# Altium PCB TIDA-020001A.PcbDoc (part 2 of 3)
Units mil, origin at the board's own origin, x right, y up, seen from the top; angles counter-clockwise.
Board outline 11050 x 5518 mil, 4 copper layers (Top Layer, PWR, GND, Bottom Layer), stack 61.434 mil thick; 283 components, 210 nets, 883 pads, 1184 vias.
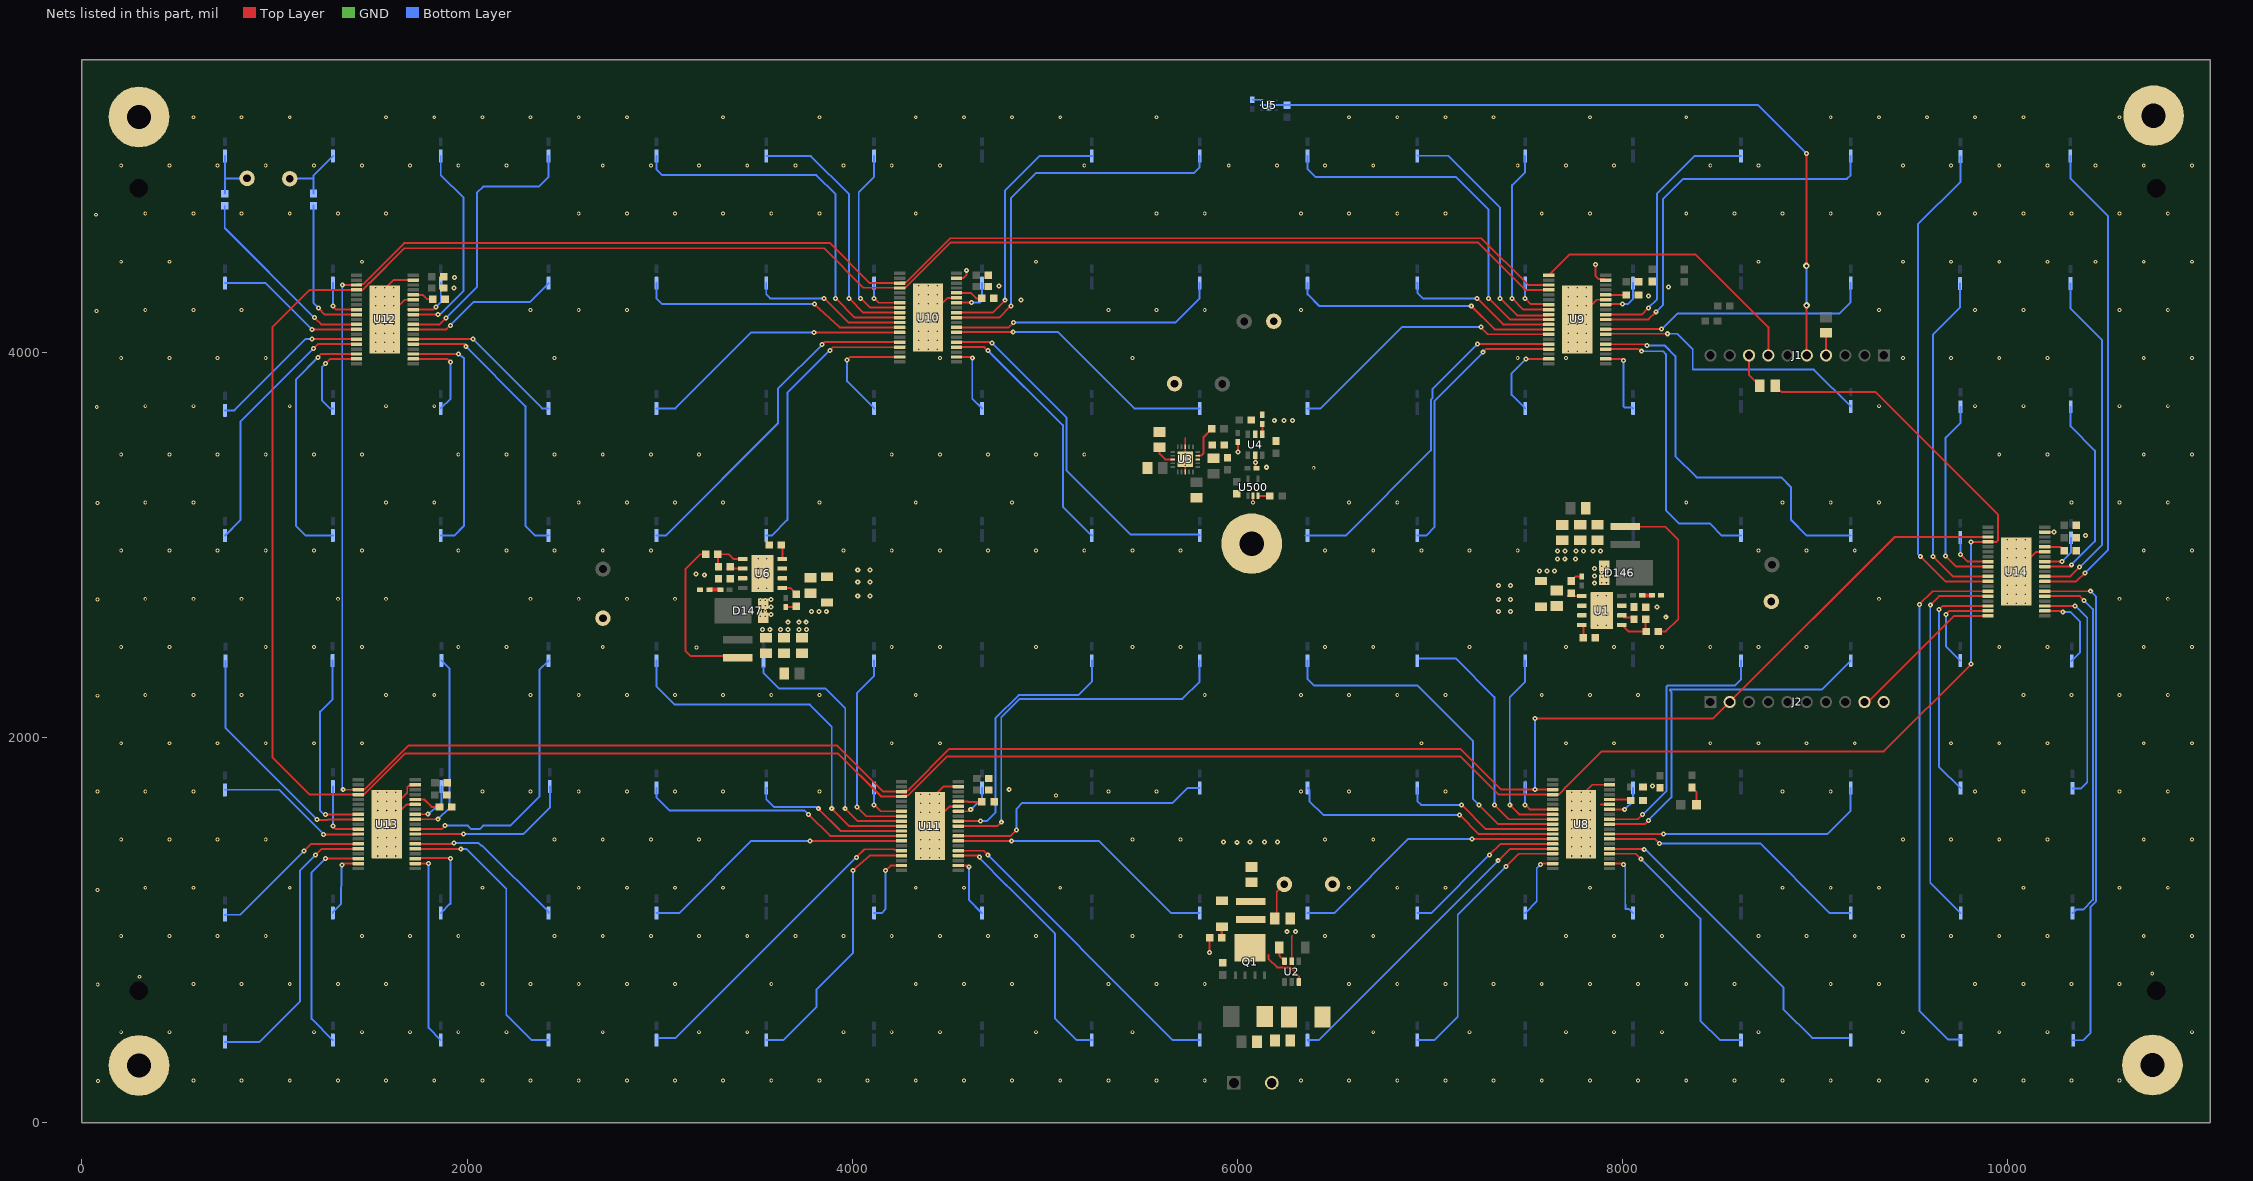
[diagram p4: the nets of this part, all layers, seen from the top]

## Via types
v1: diameter 20, hole 10, Top Layer to Bottom Layer, tented both sides, 504 vias
v2: diameter 26, hole 10, Top Layer to Bottom Layer, tented both sides, 472 vias
v3: diameter 19.68, hole 7.87, Top Layer to Bottom Layer, tented both sides, 205 vias
v4: diameter 34, hole 16, Top Layer to Bottom Layer, tented both sides, 2 vias
v5: diameter 19.68, hole 7.87, Top Layer to Bottom Layer, 1 vias

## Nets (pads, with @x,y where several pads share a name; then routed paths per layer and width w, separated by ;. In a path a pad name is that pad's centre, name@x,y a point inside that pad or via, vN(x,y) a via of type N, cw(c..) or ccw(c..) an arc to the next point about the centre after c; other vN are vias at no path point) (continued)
GCLK: R27.1 U8.4 U9.4 U10.4 U11.4 U12.4 U13.4 U14.4 | length 21192.8
  Top Layer w10: U9.4@7615.92,4323.25 7493.68,4323.25 7247.05,4569.88 4511.18,4569.88 4274.55,4333.25 U10.4@4245.92,4333.25 4244.53,4334.65 4058.07,4334.65 3853.35,4539.37 1674.21,4539.37 1493.72,4358.88 1490.77,4358.88 1482.82,4350.92 1482.82,4347.98 1458.1,4323.25 U12.4@1425.92,4323.25 1183.49,4323.25 989.17,4128.94 989.17,1896.65 1182.09,1703.74 1346.53,1703.74 1346.93,1703.35 1367.64,1703.35 1368.03,1703.74 1435.44,1703.74 U13.4@1435.92,1703.25 1464.55,1703.25 1677.63,1916.34 3927.17,1916.34 4150.25,1693.25 U11.4@4255.92,1693.25 4260.65,1697.99 4289.28,1697.99 4492.87,1901.57 7156.74,1901.57 7355.06,1703.25 U8.4@7635.92,1703.25 7666.84,1703.25 7692.82,1729.24 7692.82,1730.92 7700.77,1738.88 7702.46,1738.88 7890.75,1927.17 9355.32,1927.17 v2(9809.06,2380.91) ; R27.1@8790.98,3825.79 8823.46,3793.31 9312.01,3793.31 9948.82,3156.5 9948.82,3023.62 9939.96,3014.76 9896.15,3014.76 U14.4@9896.04,3014.87 v2(9809.06,3014.87)
  Bottom Layer w10: v2(9809.06,2380.91) v2(9809.06,3014.87)
GND: C1.2 C4.2 C5.1 C7.2 C8.2 C9.2 C11.2 C12.2 C13.2 C14.2 C15.2 C16.2 C17.2 C19.2 C21.2 C22.1 C23.2 C24.2 C25.2 C26.2 C27.2 C28.2 C29.2 C30.2 C31.2 C40.2 C41.2 C42.2 C43.2 C44.2 C45.2 C46.2 C47.2 C48.2 C49.2 C77.2 C88.2 C500.2 D145.1 D146.1 D146.2 D147.1 D147.2 H1.1 H2.1 H3.1 H4.1 H5.1 J2.10 R3.1 R5.1 R7.1 R8.1 R10.1 R11.1 R12.1 R14.1 R16.1 R18.1 R22.1 R23.1 R25.1 R31.1 TP4.1 TP5.1 TP7.1 TP9.1 TP11.1 U1.7 U1.9@7891.73,2658.86 U2.2 U3.8 U3.18 U3.21 U4.2 U5.2 U5.3 U5.7 U6.7 U6.9@3534.15,2851.35 U8.33 U8.37 U8.39 U9.33 U9.37 U9.39 U10.33 U10.37 U10.39 U11.33 U11.37 U11.39 U12.33 U12.37 U12.39 U13.33 U13.37 U13.39 U14.33 U14.37 U14.39 U500.2 Vbatt1.2 | length 3313.3
  Top Layer w10: U12.39@1573.56,4169.71 1675.92,4272.07 U12.33@1721.2,4272.07 ; v3(1573.56,4193.33) v3(1573.56,4240.58) v3(1573.56,4287.82) 1573.56,4330.45 1617.54,4374.43 U12.37@1721.2,4374.43 ; U13.33@1731.2,1652.07 1685.92,1652.07 U13.39@1583.56,1549.71 v3(1583.56,1573.33) 1583.56,1606.8 1689.67,1712.91 1689.67,1741.53 1697.84,1749.7 1726.47,1749.7 U13.37@1731.2,1754.43 ; U10.39@4393.56,4179.71 4495.92,4282.07 U10.33@4541.2,4282.07 ; v3(4393.56,4297.82) U10.39@4393.56,4300.56 ; U10.37@4541.2,4384.43 4576.2,4384.43 4576.77,4383.86 4592.52,4399.61 v2(4592.52,4425.2) ; U11.33@4551.2,1642.07 4505.92,1642.07 U11.39@4403.56,1539.71 v3(4403.56,1563.33) v3(4403.56,1610.58) v3(4403.56,1657.82) 4403.56,1675.21 4472.78,1744.43 U11.37@4551.2,1744.43 ; U3.18@5728.93,3378.02 v3(5728.93,3412.47) U3.21@5728.93,3442.98 v3(5728.93,3473.49) U3.8@5728.93,3507.94 5728.93,3554.87 ; v2(5855.31,883.86) R31.1@5855.31,959.65 ; C9.2@6000.94,3533.68 6002.95,3531.67 v2(6002.95,3482.28) ; v1(6079.72,3219.64) 6080.71,3220.62 U500.2@6080.71,3253.94 ; U4.2@6091.8,3465.42 6093.5,3448.82 v2(6093.5,3427.17) 6093.5,3425.2 6093.5,3409.43 C7.2@6099.41,3397.64 ; U2.2@6281.5,838.58 6281.5,967.52 6282.17,968.19 ; U9.39@7763.56,4169.71 7865.92,4272.07 U9.33@7911.2,4272.07 ; U8.39@7783.56,1549.71 v3(7783.56,1573.33) v3(7783.56,1620.58) v3(7783.56,1667.82) 7783.56,1696.95 7841.05,1754.43 U8.37@7931.2,1754.43 ; v2(7858.87,4455.79) 7858.27,4396.69 7875.75,4379.2 ; 7875.75,4379.17 7906.47,4379.17 U9.37@7911.2,4374.43 ; 7885.92,1652.07 U8.33@7931.2,1652.07 ; U14.39@10043.68,2861.33 10146.04,2963.69 U14.33@10191.32,2963.69 ; U14.37@10191.32,3066.05 10192.19,3066.93 v2(10238.19,3066.93)
  GND w10: v3@10089.36,2981 v3(10090.92,2979.44) v3@10092.81,2981.32
  Bottom Layer w10: C11.2@6077.34,5310.63 6123.62,5310.63 U5.3@6126.23,5308.02 U5.2@6126.23,5282.24 U5.7@6163.63,5282.24
  other v1: 83.66,215.55 579.72,219.64 829.72,219.64 1079.72,219.64 1329.72,219.64 1579.72,219.64 1829.72,219.64 2079.72,219.64 2329.72,219.64 2579.72,219.64 2829.72,219.64 3079.72,219.64 3329.72,219.64 3579.72,219.64 3829.72,219.64 4079.72,219.64 4329.72,219.64 4579.72,219.64 4829.72,219.64 5079.72,219.64 5329.72,219.64 5579.72,219.64 5829.72,219.64 6329.72,219.64 6579.72,219.64 6829.72,219.64 7079.72,219.64 7329.72,219.64 7579.72,219.64 7829.72,219.64 8079.72,219.64 8329.72,219.64 8579.72,219.64 8829.72,219.64 9079.72,219.64 9329.72,219.64 9579.72,219.64 9829.72,219.64 10079.72,219.64 10329.72,219.64 10579.72,219.64 204.72,469.64 454.72,469.64 1204.72,469.64 1454.72,469.64 1704.72,469.64 1954.72,469.64 2204.72,469.64 2704.72,469.64 3204.72,469.64 3454.72,469.64 3954.72,469.64 4204.72,469.64 4454.72,469.64 4954.72,469.64 5454.72,469.64 6704.72,469.64 7204.72,469.64 7704.72,469.64 7954.72,469.64 8204.72,469.64 8704.72,469.64 9454.72,469.64 9954.72,469.64 10204.72,469.64 10954.72,469.64 82.68,716.54 579.72,719.64 829.72,719.64 1079.72,719.64 1329.72,719.64 1579.72,719.64 2079.72,719.64 2329.72,719.64 2579.72,719.64 2829.72,719.64 3079.72,719.64 3579.72,719.64 4329.72,719.64 4579.72,719.64 4829.72,719.64 5329.72,719.64 5579.72,719.64 5829.72,719.64 6579.72,719.64 6829.72,719.64 7079.72,719.64 7329.72,719.64 7579.72,719.64 7829.72,719.64 8079.72,719.64 8329.72,719.64 8579.72,719.64 9079.72,719.64 9329.72,719.64 9829.72,719.64 10079.72,719.64 10329.72,719.64 10579.72,719.64 300.2,757.41 10749.02,773.62 204.72,969.64 454.72,969.64 704.72,969.64 954.72,969.64 1454.72,969.64 1704.72,969.64 1954.72,969.64 2454.72,969.64 2704.72,969.64 2954.72,969.64 3204.72,969.64 3454.72,969.64 3704.72,969.64 3954.72,969.64 4204.72,969.64 4454.72,969.64 4704.72,969.64 4954.72,969.64 5454.72,969.64 5704.72,969.64 6454.72,969.64 6704.72,969.64 7704.72,969.64 7954.72,969.64 8204.72,969.64 8704.72,969.64 8954.72,969.64 9204.72,969.64 9454.72,969.64 9704.72,969.64 9954.72,969.64 10204.72,969.64 10704.72,969.64 10954.72,969.64 81.69,1207.68 329.72,1219.64 579.72,1219.64 1079.72,1219.64 2079.72,1219.64 2579.72,1219.64 2829.72,1219.64 3079.72,1219.64 3329.72,1219.64 4329.72,1219.64 4579.72,1219.64 5079.72,1219.64 6579.72,1219.64 6829.72,1219.64 7079.72,1219.64 7829.72,1219.64 8829.72,1219.64 9079.72,1219.64 9329.72,1219.64 10079.72,1219.64 10579.72,1219.64 10829.72,1219.64 204.72,1469.64 454.72,1469.64 704.72,1469.64 954.72,1469.64 2454.72,1469.64 2704.72,1469.64 2954.72,1469.64 3204.72,1469.64 5454.72,1469.64 5704.72,1469.64 6454.72,1469.64 6704.72,1469.64 9454.72,1469.64 9704.72,1469.64 9954.72,1469.64 10204.72,1469.64 10704.72,1469.64 10954.72,1469.64 5058.07,1698.82 81.69,1719.49 329.72,1719.64 579.72,1719.64 2079.72,1719.64 2329.72,1719.64 2579.72,1719.64 2829.72,1719.64 3079.72,1719.64 3329.72,1719.64 3829.72,1719.64 5329.72,1719.64 5579.72,1719.64 6329.72,1719.64 6579.72,1719.64 7079.72,1719.64 8829.72,1719.64 9079.72,1719.64 9829.72,1719.64 10079.72,1719.64 10579.72,1719.64 10829.72,1719.64 204.72,1969.64 454.72,1969.64 704.72,1969.64 954.72,1969.64 1204.72,1969.64 1454.72,1969.64 4204.72,1969.64 4454.72,1969.64 6954.72,1969.64 7704.72,1969.64 7954.72,1969.64 8454.72,1969.64 8704.72,1969.64 8954.72,1969.64 9204.72,1969.64 9704.72,1969.64 9954.72,1969.64 10204.72,1969.64 10704.72,1969.64 10954.72,1969.64 81.69,2216.54 329.72,2219.64 579.72,2219.64 829.72,2219.64 1579.72,2219.64 1829.72,2219.64 2329.72,2219.64 2579.72,2219.64 2829.72,2219.64 3079.72,2219.64 3329.72,2219.64 3579.72,2219.64 3829.72,2219.64 4329.72,2219.64 5829.72,2219.64 6329.72,2219.64 6579.72,2219.64 6829.72,2219.64 7079.72,2219.64 7579.72,2219.64 7829.72,2219.64 8079.72,2219.64 10079.72,2219.64 10329.72,2219.64 10579.72,2219.64 10829.72,2219.64 3190.94,2466.69 204.72,2469.64 454.72,2469.64 954.72,2469.64 1204.72,2469.64 1454.72,2469.64 1954.72,2469.64 2204.72,2469.64 2704.72,2469.64 4204.72,2469.64 4454.72,2469.64 4954.72,2469.64 5454.72,2469.64 5704.72,2469.64 6454.72,2469.64 6704.72,2469.64 7204.72,2469.64 7704.72,2469.64 7954.72,2469.64 8204.72,2469.64 8454.72,2469.64 8704.72,2469.64 8954.72,2469.64 9954.72,2469.64 10204.72,2469.64 10704.72,2469.64 10954.72,2469.64 81.69,2715.55 329.72,2719.64 579.72,2719.64 829.72,2719.64 1329.72,2719.64 1579.72,2719.64 2329.72,2719.64 2579.72,2719.64 2829.72,2719.64 3079.72,2719.64 9329.72,2719.64 10579.72,2719.64 10829.72,2719.64 204.72,2969.64 454.72,2969.64 704.72,2969.64 954.72,2969.64 1204.72,2969.64 1454.72,2969.64 1954.72,2969.64 2204.72,2969.64 2454.72,2969.64 2704.72,2969.64 2954.72,2969.64 3954.72,2969.64 4204.72,2969.64 4454.72,2969.64 4704.72,2969.64 4954.72,2969.64 5204.72,2969.64 5454.72,2969.64 5704.72,2969.64 6454.72,2969.64 6704.72,2969.64 6954.72,2969.64 7204.72,2969.64 7454.72,2969.64 8704.72,2969.64 8954.72,2969.64 9204.72,2969.64 10704.72,2969.64 10954.72,2969.64 81.69,3216.54 329.72,3219.64 579.72,3219.64 1579.72,3219.64 1829.72,3219.64 2579.72,3219.64 2829.72,3219.64 3079.72,3219.64 3329.72,3219.64 3829.72,3219.64 4329.72,3219.64 4829.72,3219.64 6579.72,3219.64 6829.72,3219.64 8329.72,3219.64 8829.72,3219.64 9079.72,3219.64 9329.72,3219.64 10329.72,3219.64 10579.72,3219.64 10829.72,3219.64 6395.67,3399.61 204.72,3469.64 454.72,3469.64 704.72,3469.64 954.72,3469.64 1204.72,3469.64 1454.72,3469.64 1954.72,3469.64 2204.72,3469.64 2454.72,3469.64 2704.72,3469.64 2954.72,3469.64 3204.72,3469.64 4204.72,3469.64 4454.72,3469.64 4704.72,3469.64 4954.72,3469.64 5204.72,3469.64 9954.72,3469.64 10204.72,3469.64 10704.72,3469.64 10954.72,3469.64 77.76,3714.57 329.72,3719.64 579.72,3719.64 1079.72,3719.64 1579.72,3719.64 1829.72,3719.64 9329.72,3719.64 9829.72,3719.64 10079.72,3719.64 10579.72,3719.64 10829.72,3719.64 204.72,3969.64 454.72,3969.64 704.72,3969.64 954.72,3969.64 2454.72,3969.64 4454.72,3969.64 5454.72,3969.64 7454.72,3969.64 7704.72,3969.64 9454.72,3969.64 9704.72,3969.64 9954.72,3969.64 10204.72,3969.64 10704.72,3969.64 10954.72,3969.64 76.77,4213.58 329.72,4219.64 579.72,4219.64 829.72,4219.64 2329.72,4219.64 2579.72,4219.64 2829.72,4219.64 5329.72,4219.64 5579.72,4219.64 5829.72,4219.64 6329.72,4219.64 9329.72,4219.64 9829.72,4219.64 10079.72,4219.64 10579.72,4219.64 10829.72,4219.64 204.72,4469.64 454.72,4469.64 1454.72,4469.64 4954.72,4469.64 8704.72,4469.64 9454.72,4469.64 9704.72,4469.64 9954.72,4469.64 10204.72,4469.64 10454.72,4469.64 10704.72,4469.64 10954.72,4469.64 73.82,4713.58 329.72,4719.64 579.72,4719.64 829.72,4719.64 1079.72,4719.64 1329.72,4719.64 1579.72,4719.64 2579.72,4719.64 2829.72,4719.64 3079.72,4719.64 3329.72,4719.64 3579.72,4719.64 3829.72,4719.64 4329.72,4719.64 5579.72,4719.64 5829.72,4719.64 6329.72,4719.64 6579.72,4719.64 6829.72,4719.64 7079.72,4719.64 7579.72,4719.64 7829.72,4719.64 8329.72,4719.64 8579.72,4719.64 8829.72,4719.64 9079.72,4719.64 9329.72,4719.64 9829.72,4719.64 10079.72,4719.64 10329.72,4719.64 10579.72,4719.64 10829.72,4719.64 204.72,4969.64 454.72,4969.64 704.72,4969.64 954.72,4969.64 1204.72,4969.64 1454.72,4969.64 1704.72,4969.64 1954.72,4969.64 2204.72,4969.64 2704.72,4969.64 2954.72,4969.64 3204.72,4969.64 3454.72,4969.64 3704.72,4969.64 3954.72,4969.64 4204.72,4969.64 4454.72,4969.64 5204.72,4969.64 5954.72,4969.64 6204.72,4969.64 6454.72,4969.64 6704.72,4969.64 7454.72,4969.64 7704.72,4969.64 7954.72,4969.64 8454.72,4969.64 8704.72,4969.64 9454.72,4969.64 9704.72,4969.64 9954.72,4969.64 10204.72,4969.64 10454.72,4969.64 10704.72,4969.64 10954.72,4969.64 579.72,5219.64 829.72,5219.64 1079.72,5219.64 1579.72,5219.64 1829.72,5219.64 2079.72,5219.64 2329.72,5219.64 2579.72,5219.64 2829.72,5219.64 3329.72,5219.64 3829.72,5219.64 4329.72,5219.64 4579.72,5219.64 4829.72,5219.64 5079.72,5219.64 5579.72,5219.64 6579.72,5219.64 6829.72,5219.64 7079.72,5219.64 7329.72,5219.64 7829.72,5219.64 8329.72,5219.64 9079.72,5219.64 9329.72,5219.64 9579.72,5219.64 9829.72,5219.64 10079.72,5219.64 10579.72,5219.64
  other v2: 6257.87,991.14 6300.24,991.14 4814.96,1730.32 8154.53,1747.05 3533.46,2560.04 3571.79,2560.04 3627.95,2561.02 3667.32,2561.02 3723.43,2561.02 3761.75,2561.02 3667.11,2598.04 3722.9,2598.04 3760.99,2598.04 8223.43,2624.02 3578.14,2638.95 3788.5,2653.54 3826.83,2653.54 3865.16,2653.54 8177.17,2676.18 3578.14,2677.28 3578.14,2715.61 7854.25,2800.47 7854.25,2838.8 3231.8,2842.35 3189.47,2847.54 7568.96,2864.17 7607.28,2864.17 7645.61,2864.17 7854.25,2877.13 7660.94,2925.52 7699.03,2925.52 7754.82,2925.52 7846.46,2967.52 7884.78,2967.52 7662.4,2968.5 7700.73,2968.5 7758.11,2968.5 7796.44,2968.5 10401.57,3048.23 6150.59,3402.56 6190.94,3644.69 6241.14,3644.69 6286.42,3644.69 4875.85,4271.05 8134.84,4292.32 1933.07,4333.66 8237.2,4338.58 4760.83,4342.52 1934.06,4387.8
  other v3: 4356.32,1374.36 4403.56,1374.36 4450.8,1374.36 1536.32,1384.36 1583.56,1384.36 1630.8,1384.36 7736.32,1384.36 7783.56,1384.36 7830.81,1384.36 4356.32,1421.6 4403.56,1421.6 4450.8,1421.6 1536.32,1431.6 1583.56,1431.6 1630.8,1431.6 7736.32,1431.6 7783.56,1431.6 7830.81,1431.6 4356.32,1468.84 4403.56,1468.84 4450.8,1468.84 1536.32,1478.84 1583.56,1478.84 1630.8,1478.84 7736.32,1478.84 7783.56,1478.84 7830.81,1478.84 4356.32,1516.09 4403.56,1516.09 4450.8,1516.09 1536.32,1526.09 1630.8,1526.09 7736.32,1526.09 7783.56,1526.09 7830.81,1526.09 4356.32,1563.33 4450.8,1563.33 1536.32,1573.33 1630.8,1573.33 7736.32,1573.33 7830.81,1573.33 4356.32,1610.58 4450.8,1610.58 1536.32,1620.58 1583.56,1620.58 1630.8,1620.58 7736.32,1620.58 7830.81,1620.58 4356.32,1657.82 4450.8,1657.82 1536.32,1667.82 1583.56,1667.82 1630.8,1667.82 7736.32,1667.82 7830.81,1667.82 4356.32,1705.06 4403.56,1705.06 4450.8,1705.06 1536.32,1715.06 1583.56,1715.06 1630.8,1715.06 7736.32,1715.06 7783.56,1715.06 7830.81,1715.06 7870.08,2582.09 7913.39,2582.09 3522.55,2627.86 3548.16,2627.82 7870.08,2633.27 7913.39,2633.27 3522.55,2656.99 3548.14,2656.99 3522.4,2684.06 3548.01,2684.01 7870.08,2684.45 7913.39,2684.45 9996.43,2695.97 10043.68,2695.97 10090.92,2695.97 3522.4,2713.19 3547.99,2713.19 7870.08,2735.63 7913.39,2735.63 9996.43,2743.22 10043.68,2743.22 10090.92,2743.22 3512.5,2774.57 3555.8,2774.57 9996.43,2790.46 10043.68,2790.46 10090.92,2790.46 7890.08,2802.88 7915.69,2802.84 3512.5,2825.76 3555.8,2825.76 7890.08,2832.02 7915.67,2832.02 9996.43,2837.71 10043.68,2837.71 10090.92,2837.71 7889.93,2859.08 7915.54,2859.04 3512.5,2876.94 3555.8,2876.94 9996.43,2884.95 10043.68,2884.95 10090.92,2884.95 7889.93,2888.21 7915.52,2888.21 3512.5,2928.12 3555.8,2928.12 9996.43,2932.19 10043.68,2932.19 10090.92,2932.19 9996.43,2979.44 10043.68,2979.44 9996.43,3026.68 10043.68,3026.68 10090.92,3026.68 5698.42,3442.98 5759.44,3442.98 1526.32,4004.36 1573.56,4004.36 1620.81,4004.36 7716.32,4004.36 7763.56,4004.36 7810.8,4004.36 4346.32,4014.36 4393.56,4014.36 4440.8,4014.36 1526.32,4051.6 1573.56,4051.6 1620.81,4051.6 7716.32,4051.6 7763.56,4051.6 7810.8,4051.6 4346.32,4061.6 4393.56,4061.6 4440.8,4061.6 1526.32,4098.84 1573.56,4098.84 1620.81,4098.84 7716.32,4098.84 7763.56,4098.84 7810.8,4098.84 4346.32,4108.84 4393.56,4108.84 4440.8,4108.84 1526.32,4146.09 1573.56,4146.09 1620.81,4146.09 7716.32,4146.09 7763.56,4146.09 7810.8,4146.09 4346.32,4156.09 4393.56,4156.09 4440.8,4156.09 1526.32,4193.33 1620.81,4193.33 7716.32,4193.33 7763.56,4193.33 7810.8,4193.33 4346.32,4203.33 4393.56,4203.33 4440.8,4203.33 1526.32,4240.58 1620.81,4240.58 7716.32,4240.58 7763.56,4240.58 7810.8,4240.58 4346.32,4250.58 4393.56,4250.58 4440.8,4250.58 1526.32,4287.82 1620.81,4287.82 7716.32,4287.82 7763.56,4287.82 7810.8,4287.82 4346.32,4297.82 4440.8,4297.82 1526.32,4335.06 1573.56,4335.06 1620.81,4335.06 7716.32,4335.06 7763.56,4335.06 7810.8,4335.06 4346.32,4345.06 4393.56,4345.06 4440.8,4345.06 6163.63,5266.49 6163.63,5297.99
  other v5: 1583.56,1526.09
INT: J1.5 R17.1 U5.5 | length 3905.9
  Top Layer w10: v4(8953.74,4447.83) v2(8953.74,5031.5) ; v4(8954.72,4243.11) 8954.72,3984.28 J1.5@8955.68,3983.33
  Bottom Layer w10: U5.5@6201.03,5282.24 6256.54,5282.24 R17.1@6256.97,5282.67 8702.57,5282.67 v2(8953.74,5031.5) ; v4(8953.74,4447.83) 8953.74,4244.09 v4(8954.72,4243.11)
LATCH: J2.2 U8.3 U9.3 U10.3 U11.3 U12.3 U13.3 U14.3 | length 19026.5
  Top Layer w10: v2(1352.36,4348.43) 1421.98,4348.43 1424.16,4350.61 U12.3@1425.92,4348.84 1430.66,4353.58 1461.43,4353.58 1673.8,4565.94 3884.84,4565.94 4091.94,4358.84 U10.3@4245.92,4358.84 4250.65,4363.58 4280.83,4363.58 4508.79,4591.54 7265.75,4591.54 7508.44,4348.84 U9.3@7615.92,4348.84 ; v2(1357.28,1728.35) 1434.45,1728.35 1435.44,1729.33 U13.3@1435.92,1728.84 1466.1,1728.84 1694.93,1957.68 3923.23,1957.68 4162.06,1718.84 U11.3@4255.92,1718.84 4260.65,1723.58 4289.28,1723.58 4297.45,1731.75 4297.45,1734.46 4503.94,1940.94 7157.48,1940.94 7369.09,1729.33 7544.3,1729.33 v2(7544.79,1728.84) U8.3@7635.92,1728.84 ; v2(7544.29,2098.43) 8469.43,2098.43 J2.2@8555,2184 9411.46,3040.46 9831.66,3040.46 9832.16,3039.96 9852.88,3039.96 9853.38,3040.46 U14.3@9896.04,3040.46
  Bottom Layer w10: v2(1352.36,4348.43) 1352.36,1733.27 v2(1357.28,1728.35) ; v2(7544.29,2098.43) 7544.79,2097.93 v2(7544.79,1728.84)
MISO: J2.9 U14.19 | length 826.2
  Top Layer w10: J2.9@9255,2184 9273.57,2184 9720.58,2631.01 U14.19@9896.04,2631.01
MOSI: J1.7 U9.1 | length 1486.9
  Top Layer w10: U9.1@7615.92,4400.03 7722.79,4506.89 8378.94,4506.89 8755.68,4130.15 J1.7@8755.68,3983.33
NetC1_1: C1.1 R6.2 | length 58.4
  Top Layer w20: R6.2@8093.5,2737.2 8151.83,2737.2 C1.1@8151.87,2737.25
NetC2_1: C2.1 U1.1 | length 74.1
  Top Layer w10: C2.1@7714.33,2733.86 U1.1@7788.39,2733.86
NetC2_2: C2.2 R28.1 | length 63.9
  Top Layer w10: C2.2@7732.28,2812.01 7755.91,2835.63 R28.1@7786.42,2835.63
NetC3_2: C3.2 C12.1
NetC4_1: C4.1 C5.2 C21.1 C22.2 R29.2 U1.2 U1.3 U6.2 U6.3
  other v2: 5997.05,1455.71 5927.17,1456.69 6065.94,1456.69 6139.76,1456.69 6207.68,1457.68 7355.31,2654.53 7418.31,2654.53 7355.31,2716.54 7418.31,2716.54 4028.54,2734.25 4091.54,2734.25 7355.31,2789.37 7418.31,2789.37 4028.54,2807.09 4091.54,2807.09 4028.54,2869.09 4091.54,2869.09
NetC6_2: C6.2 U2.1 | length 82.3
  Top Layer w10: C6.2@6217.02,909.7 6217.02,865.65 U2.1@6244.09,838.58
NetC8_1: C8.1 U4.4 | length 54.5
  Top Layer w10: C8.1@6128.88,3628 6128.88,3574 U4.4@6129.2,3573.69
NetC10_2: C10.2 R2.1 R3.2 U3.3
NetC13_1: C13.1 U1.6 | length 74.4
  Top Layer w10: U1.6@7995.08,2633.86 8005.91,2623.03 C13.1@8064.96,2623.03
NetC14_1: C14.1 C15.1 C16.1 L2.2 R9.1 R30.1 | length 845.1
  Top Layer w10: L2.2@8013.78,3094.87 8015.14,3093.5 8221.46,3093.5 8288.39,3026.57 8288.39,2804.13 8288.39,2614.17 8224.41,2550.2 R9.1@8185.04,2550.2
NetC17_1: C17.1 L1.1 Q1.5 R1.2 TP2.1 U2.4 | length 440.7
  Top Layer w10: 6160.51,871.77 6160.51,851.3 6205.71,806.1 6272.64,806.1 6318.9,759.84 U2.4@6318.9,730.31 ; C17.1@6203.74,1059.06 6203.74,1197.83 TP2.1@6243.11,1237.2
NetC18_1: C18.1 L1.2 R29.1
NetC18_2: C18.2 R31.2 | length 58.5
  Top Layer w12: R31.2@5918.31,959.65 5918.31,1016.73 C18.2@5919.29,1017.72
NetC19_1: C19.1 R19.2 | length 57.5
  Top Layer w20: C19.1@3257.87,2767.72 3313.98,2767.72 R19.2@3314.96,2766.73
NetC20_1: C20.1 U6.1 | length 85.5
  Top Layer w10: U6.1@3637.5,2776.35 3677.39,2776.35 C20.1@3709.65,2744.09
NetC20_2: C20.2 R32.1 | length 52.2
  Top Layer w10: R32.1@3657.48,2677.17 C20.2@3709.65,2677.17
NetC23_1: C23.1 U6.6 | length 77.5
  Top Layer w10: C23.1@3353.35,2876.35 U6.6@3430.8,2876.35
NetC26_1: C26.1 C27.1 C28.1 L3.2 R21.1 R33.1 | length 798
  Top Layer w10: R21.1@3239.17,2950.79 3210.63,2950.79 3133.86,2874.02 3133.86,2448.82 3161.06,2421.62 L3.2@3358.27,2422.44
NetC31_1: C31.1 U3.13 | length 114.8
  Top Layer w10: C31.1@5595.18,3505.91 5595.18,3471.91 5624.1,3442.98 U3.13@5663.97,3442.98
NetD01_1: D01.1 R57.1 | length 99.8
  Top Layer w10: R57.1@8359.25,1740.16 8383.86,1715.55 D01.1@8383.86,1650.59
NetD145_2: D145.2 D148.2
NetJ1_4: J1.4 R26.2 | length 116.7
  Top Layer w10: J1.4@9055.92,3983.57 R26.2@9055.92,4100.3
NetJ1_8: J1.8 R27.2 | length 180.4
  Top Layer w10: J1.8@8655.68,3983.33 8655.68,3881.09 R27.2@8710.98,3825.79
NetR4_1: R4.1 U4.5
NetR5_2: R5.2 U9.34 | length 107.5
  Top Layer w10: U9.34@7911.2,4297.24 R5.2@8018.7,4297.24
NetR7_2: R7.2 U11.34 | length 120.5
  Top Layer w10: U11.34@4551.2,1667.66 4600.05,1667.66 4603.35,1664.37 R7.2@4670.3,1664.37
NetR8_2: R8.2 U12.34 | length 114.6
  Top Layer w10: U12.34@1721.2,4297.66 1769.27,4297.66 1792.32,4274.61 R8.2@1826.28,4274.61
NetR9_2: R9.2 R14.2 U1.5 | length 219.7
  Top Layer w10: U1.5@7995.08,2583.86 8028.74,2550.2 R9.2@8131.91,2550.2 ; R9.2@8119.09,2553.15 R14.2@8119.09,2622.05
NetR10_2: R10.2 U13.34 | length 142.2
  Top Layer w10: U13.34@1731.2,1677.66 1777.06,1677.66 1815.94,1638.78 R10.2@1857.28,1638.78
NetR11_2: R11.2 U1.4 | length 69
  Top Layer w10: U1.4@7788.39,2583.86 7795.28,2576.97 R11.2@7795.28,2517.72
NetR12_2: R12.2 U14.34 | length 109.2
  Top Layer w10: U14.34@10191.32,2989.28 10272.53,2989.28 R12.2@10292.32,2969.49
NetR13_1: R13.1 U500.3 | length 63
  Top Layer w10: U500.3@6105.31,3253.94 R13.1@6168.31,3253.94
NetR16_2: R16.2 U8.34 | length 113.4
  Top Layer w10: U8.34@7931.2,1677.66 8036.91,1677.66 R16.2@8042.32,1672.24
NetR18_2: R18.2 U10.34 | length 142.7
  Top Layer w10: U10.34@4541.2,4307.66 4614.58,4307.66 4642.72,4279.53 R18.2@4672.24,4279.53
NetR21_2: R21.2 R23.2 U6.5 | length 203.9
  Top Layer w10: R23.2@3305.42,2887.04 3302.17,2890.29 R21.2@3302.17,2950.79 3358.27,2950.79 3382.71,2926.35 U6.5@3430.8,2926.35
NetR22_2: R22.2 U6.4 | length 74.9
  Top Layer w10: R22.2@3631.59,2998.79 3637.5,2992.88 U6.4@3637.5,2926.35
NetR24_1: R24.1 U3.4 | length 180.7
  Top Layer w10: U3.4@5793.89,3462.67 5812.13,3462.67 5823.52,3474.06 5823.52,3559.16 R24.1@5866.86,3602.5
NetR34_1: R34.1 U12.9 | length 753.4
  Top Layer w10: v2(1229.33,4228.35) 1262.38,4195.3 U12.9@1425.92,4195.3
  Bottom Layer w10: R34.1@1203.74,4760.83 1203.74,4253.94 v2(1229.33,4228.35)
NetR35_1: R35.1 U12.11 | length 1006.3
  Top Layer w10: v2(1207.68,4179.13) 1242.69,4144.12 U12.11@1425.92,4144.12
  Bottom Layer w10: R35.1@742.13,4759.84 742.13,4644.69 v2(1207.68,4179.13)
OUTA0: D97.1 U12.8 | length 248.7
  Top Layer w10: v2(1303.56,4239.71) 1322.38,4220.89 U12.8@1425.92,4220.89
  Bottom Layer w10: v2(1303.56,4239.71) D97.1@1303.56,4358.21
OUTA0/1: D113.1 U13.8 | length 1012.3
  Top Layer w10: v2(1264.76,1600.89) U13.8@1435.92,1600.89
  Bottom Layer w10: v2(1264.76,1600.89) 1256.39,1600.89 1237.47,1619.81 1237.47,2133.62 1302.17,2198.31 D113.1@1302.17,2398.62 ; D113.1@1303.56,2381.82 D113.1@1303.85,2382.11
OUTA0/3: D129.1 U14.8 | length 245.1
  Top Layer w10: v2(9753.68,2949.33) 9790.5,2912.51 U14.8@9896.04,2912.51
  Bottom Layer w10: v2(9753.68,2949.33) D129.1@9753.68,3036.83
OUTA1: D99.1 R35.2 TP12.1 | length 311.9
  Bottom Layer w10: R35.2@742.13,4822.83 743.56,4824.27 743.56,4899.61 ; D99.1@743.56,5018.21 743.56,4899.61 ; TP12.1@858.27,4902.56 746.51,4902.56 743.56,4899.61
OUTA1/1: D115.1 U13.11 | length 343.8
  Top Layer w10: v2(1303.56,1539.71) 1319.15,1524.12 U13.11@1435.92,1524.12
  Bottom Layer w10: v2(1303.56,1539.71) 1303.95,1540.09 D115.1@1303.95,1744.51
OUTA1/3: D131.1 U14.11 | length 1804
  Top Layer w10: v2(9609.68,2940.33) 9714.27,2835.74 U14.11@9896.04,2835.74
  Bottom Layer w10: v2(9609.68,2940.33) 9609.68,4091.33 9751.68,4233.33 D131.1@9751.68,4355.83
OUTA2: D101.1 U12.14 | length 835.3
  Top Layer w10: v2(1195.92,4067.35) U12.14@1425.92,4067.35
  Bottom Layer w10: D101.1@743.56,3698.21 792.06,3698.21 1161.2,4067.35 v2(1195.92,4067.35)
OUTA2/1: D117.1 U13.14 | length 844.7
  Top Layer w10: v2(1153.56,1409.71) 1191.2,1447.35 U13.14@1435.92,1447.35
  Bottom Layer w10: D117.1@743.56,1078.21 823.56,1079.71 v2(1153.56,1409.71)
OUTA2/3: D133.1 U14.14 | length 2771.9
  Top Layer w10: v2(9539.68,2690.33) 9608.32,2758.97 U14.14@9896.04,2758.97
  Bottom Layer w10: v2(9539.68,2690.33) 9539.68,580.4 9688.98,431.1 9750.41,431.1 D133.1@9753.68,427.83
OUTA3: D103.1 U12.17 | length 1339.8
  Top Layer w10: v2(1226.38,3972.53) 1244.43,3990.58 U12.17@1425.92,3990.58
  Bottom Layer w10: v2(1226.38,3972.53) 1113.19,3859.34 1113.19,3097.44 1162.42,3048.21 D103.1@1303.56,3048.21
OUTA3/1: D119.1 U13.17 | length 1188.8
  Top Layer w10: v2(1264.43,1370.58) U13.17@1435.92,1370.58
  Bottom Layer w10: v2(1264.43,1370.58) 1193.56,1299.71 1193.56,538.22 D119.1@1303.56,428.22
OUTA3/3: D135.1 U14.17 | length 1235.7
  Top Layer w10: v2(9641.68,2664.33) 9659.54,2682.19 U14.17@9896.04,2682.19
  Bottom Layer w10: v2(9641.68,2664.33) 9641.68,1848.83 D135.1@9753.68,1736.83
OUTA4: D105.1 U12.22 | length 1282
  Top Layer w10: U12.22@1721.2,3990.58 v2(1954.72,3991.14)
  Bottom Layer w10: D105.1@1863.56,3048.21 1934.21,3048.21 1983.56,3097.56 1983.56,3969.71 v2(1954.72,3991.14)
OUTA4/1: D121.1 U13.22 | length 491.9
  Top Layer w10: U13.22@1731.2,1370.58 1731.2,1373.49 1910.96,1373.49 v2(1913.39,1371.06)
  Bottom Layer w10: D121.1@1863.56,1088.21 1913.39,1138.04 ; 1913.39,1135.74 1913.39,1138.04 ; v2(1913.39,1371.06) 1913.39,1138.04
OUTA4/3: D137.1 U14.22 | length 1188.9
  Top Layer w10: U14.22@10191.32,2682.19 10347.55,2682.19 v2(10348.43,2683.07)
  Bottom Layer w10: D137.1@10334.68,1735.83 10379.53,1735.83 10411.42,1767.72 10411.42,2620.08 v2(10348.43,2683.07)
OUTA5: D107.1 U12.25 | length 851.1
  Top Layer w10: U12.25@1721.2,4067.35 v2(2031.2,4067.35)
  Bottom Layer w10: v2(2031.2,4067.35) 2390.33,3708.21 D107.1@2423.56,3708.21
OUTA5/1: D123.1 U13.25 | length 848
  Top Layer w10: U13.25@1731.2,1447.35 1927.66,1447.35 v2(1932.09,1451.77)
  Bottom Layer w10: v2(1932.09,1451.77) 2060.01,1451.77 2073.02,1438.76 2078.55,1438.76 2423.56,1093.75 D123.1@2423.56,1088.22
OUTA5/3: D139.1 U14.25 | length 2673.5
  Top Layer w10: U14.25@10191.32,2758.97 v2(10429.13,2758.97) v2@10442.04,2758.97
  Bottom Layer w10: D139.1@10338.68,427.83 10390.75,427.83 10429.13,466.22 10429.13,1120.74 10457.68,1149.29 10457.68,2730.42 v2(10429.13,2758.97)
OUTA6: D109.1 U12.28 | length 1415
  Top Layer w10: U12.28@1721.2,4144.12 1857.97,4144.12 v2(1890.75,4176.9)
  Bottom Layer w10: v2(1890.75,4176.9) 2051.18,4337.33 2051.18,4827.33 2083.56,4859.71 2373.56,4859.71 2423.56,4909.71 D109.1@2423.56,5018.21
OUTA6/1: D125.1 U13.28 | length 1454.8
  Top Layer w10: U13.28@1731.2,1524.12 1867.97,1524.12 v2(1885.83,1541.98)
  Bottom Layer w10: v2(1885.83,1541.98) 2004.56,1541.98 2022.75,1523.79 2065.83,1523.79 2084.02,1541.98 2225.05,1541.98 2375.98,1692.91 2375.98,2350.64 D125.1@2423.56,2398.22
OUTA6/3: D141.1 U14.28 | length 1790
  Top Layer w10: U14.28@10191.32,2835.74 10324.09,2835.74 v2(10371.06,2883.86)
  Bottom Layer w10: D141.1@10324.68,4356.83 10324.68,4225.33 10488.34,4061.67 10488.34,2999.99 10372.21,2883.86 v2(10371.06,2883.86)
OUTA7: D111.1 U12.31 | length 256.9
  Top Layer w10: U12.31@1721.2,4220.89 1824.74,4220.89 v2(1838.1,4234.25)
  Bottom Layer w10: v2(1838.1,4234.25) 1863.56,4259.71 D111.1@1863.56,4358.22
OUTA7/1: D127.1 U13.31 | length 242
  Top Layer w10: U13.31@1731.2,1600.89 v2(1796.26,1601.38)
  Bottom Layer w10: v2(1796.26,1601.38) 1866.94,1658.27 D127.1@1866.94,1744.51
OUTA7/3: D143.1 U14.31 | length 231.3
  Top Layer w10: U14.31@10191.32,2912.51 v2(10279.86,2912.51)
  Bottom Layer w10: v2(10279.86,2912.51) 10326.68,2959.33 D143.1@10326.68,3035.83
OUTB0: D3.1 U8.9 | length 1364.5
  Top Layer w10: v2(7333.56,1649.71) 7407.97,1575.3 U8.9@7635.92,1575.3
  Bottom Layer w10: 6945.06,2409.71 7133.56,2409.71 7333.56,2209.71 v2(7333.56,1649.71)
OUTB0/1: D27.1 U9.9 | length 1300.9
  Top Layer w10: v2(7363.56,4279.71) 7451.83,4191.44 7612.07,4191.44 U9.9@7615.92,4195.3
  Bottom Layer w10: D27.1@6935.06,5019.71 7093.56,5019.71 7363.56,4749.71 v2(7363.56,4279.71)
OUTB0/2: D51.1 U10.9 | length 1345.4
  Top Layer w10: v2(3983.56,4279.71) 4057.97,4205.3 U10.9@4245.92,4205.3
  Bottom Layer w10: D51.1@3553.56,5018.21 3785.06,5018.21 3983.56,4819.71 v2(3983.56,4279.71)
OUTB0/3: D75.1 U11.9 | length 1386.7
  Top Layer w10: v2(3963.56,1629.71) 4027.97,1565.3 U11.9@4255.92,1565.3
  Bottom Layer w10: 3539.78,2336.2 D75.1@3539.78,2366.76 ; 3539.78,2350.39 3539.78,2334.04 3618.9,2254.92 3791.77,2254.92 3791.85,2255 3824.15,2255 3824.23,2254.92 3859.25,2254.92 3963.56,2150.61 v2(3963.56,1629.71)
OUTB0/4: D98.1 R34.2 TP1.1 | length 361.4
  Bottom Layer w10: TP1.1@1079.72,4900.59 1199.8,4900.59 1203.74,4896.65 ; R34.2@1203.74,4823.82 1203.74,4896.65 ; D98.1@1303.56,5018.21 1203.74,4918.39 1203.74,4896.65
OUTB0/5: D114.1 U13.9 | length 1236.9
  Top Layer w10: v2(1220.47,1574.8) 1223.38,1571.89 1276.78,1571.89 1279.69,1574.8 1435.43,1574.8 U13.9@1435.92,1575.3
  Bottom Layer w10: D114.1@746,2397.11 746,2049.27 v2(1220.47,1574.8)
OUTB0/7: D130.1 U14.9 | length 1049.3
  Top Layer w10: v2(9676.68,2941.33) 9731.09,2886.92 U14.9@9896.04,2886.92
  Bottom Layer w10: v2(9676.68,2941.33) 9676.68,3556.33 9753.68,3633.33 D130.1@9753.68,3716.83
OUTB1: D6.1 U8.12 | length 1405.9
  Top Layer w10: v2(7153.56,1597.35) 7252.38,1498.53 U8.12@7635.92,1498.53
  Bottom Layer w10: D6.1@6363.56,1738.21 6373.56,1728.21 6373.56,1669.71 6445.92,1597.35 v2(7153.56,1597.35)
OUTB1/1: D30.1 U9.12 | length 1385.9
  Top Layer w10: v2(7213.56,4239.71) 7334.74,4118.53 U9.12@7615.92,4118.53
  Bottom Layer w10: D30.1@6363.56,4358.21 6363.56,4299.71 6423.56,4239.71 v2(7213.56,4239.71)
OUTB1/2: D54.1 U10.12 | length 1400.7
  Top Layer w10: v2(3803.56,4249.71) 3934.74,4128.53 U10.12@4245.92,4128.53
  Bottom Layer w10: D54.1@2983.56,4358.22 2983.56,4279.71 3013.56,4249.71 v2(3803.56,4249.71)
OUTB1/3: D78.1 U11.12 | length 1404.2
  Top Layer w10: v2(3773.56,1599.71) 3884.74,1488.53 U11.12@4255.92,1488.53
  Bottom Layer w10: D78.1@2983.56,1738.21 2983.56,1689.71 3053.56,1619.71 3753.56,1619.71 v2(3773.56,1599.71)
OUTB1/4: D100.1 U12.12 | length 781.7
  Top Layer w10: v2(1194.74,4118.53) U12.12@1425.92,4118.53
  Bottom Layer w10: D100.1@743.56,4358.21 743.62,4358.27 869.09,4358.27 955,4358.27 v2(1194.74,4118.53)
OUTB1/5: D116.1 U13.12 | length 790.3
  Top Layer w10: v2(1256,1497) 1430.8,1497 1434.12,1500.33 U13.12@1435.92,1498.53
  Bottom Layer w10: D116.1@743.56,1728.21 1024.79,1728.21 v2(1256,1497)
OUTB1/7: D132.1 U14.12 | length 2577.5
  Top Layer w10: v2(9544.68,2940.33) 9674.86,2810.15 U14.12@9896.04,2810.15
  Bottom Layer w10: v2(9544.68,2940.33) 9532.48,2952.52 9532.48,3360.24 9532.48,4664.13 9753.68,4885.33 D132.1@9753.68,5015.83
OUTB2: D9.1 U8.15 | length 1695.9
  Top Layer w10: v2(7353.56,1359.71) 7415.61,1421.76 U8.15@7635.92,1421.76
  Bottom Layer w10: D9.1@6372.06,419.71 D9.1@6363.56,428.21 6422.06,428.21 6743.56,749.71 v2(7353.56,1359.71)
OUTB2/1: D33.1 U9.15 | length 1855.3
  Top Layer w10: v2(7245.61,4041.76) U9.15@7615.92,4041.76
  Bottom Layer w10: D33.1@6353.72,3048.21 D33.1@6363.56,3048.21 6562.06,3048.21 7003.56,3489.71 7003.56,3752.94 7011.43,3760.81 7011.43,3807.58 v2(7245.61,4041.76)
OUTB2/2: D57.1 U10.15 | length 1783.5
  Top Layer w10: v2(3843.56,4039.71) 3855.61,4051.76 U10.15@4245.92,4051.76
  Bottom Layer w10: D57.1@2983.56,3048.22 3032.07,3048.22 3613.56,3629.71 3613.56,3743.68 3614.31,3744.43 3614.31,3810.46 v2(3843.56,4039.71)
OUTB2/3: D81.1 U11.15 | length 1669.9
  Top Layer w10: v2(4021,1376.91) 4063.56,1419.47 4218.35,1419.47 4222.2,1415.62 4252.07,1415.62 U11.15@4255.92,1411.76
  Bottom Layer w10: 2995.06,439.71 3083.8,439.71 v2(4021,1376.91)
OUTB2/4: D102.1 U12.15 | length 1393.5
  Top Layer w10: v2(1203.56,4019.71) 1225.61,4041.76 U12.15@1425.92,4041.76
  Bottom Layer w10: D102.1@743.56,3048.21 823.56,3128.21 823.56,3639.71 v2(1203.56,4019.71)
OUTB2/5: D118.1 U13.15 | length 1506.4
  Top Layer w10: v2(1213.56,1389.71) 1245.61,1421.76 U13.15@1435.92,1421.76
  Bottom Layer w10: D118.1@743.56,418.21 922.06,418.21 1133.56,629.71 1133.56,1309.71 v2(1213.56,1389.71)
OUTB2/7: D134.1 U14.15 | length 1983.4
  Top Layer w10: v2(9596.68,2687.33) 9642.73,2733.37 U14.15@9896.04,2733.37
  Bottom Layer w10: v2(9596.68,2687.33) 9596.68,1245.83 D134.1@9754.68,1087.83
OUTB3: D12.1 U8.18 | length 349.2
  Top Layer w10: v2(7573.56,1339.71) 7578.84,1344.99 U8.18@7635.92,1344.99
  Bottom Layer w10: D12.1@7493.56,1088.21 7553.56,1148.21 7553.56,1319.71 v2(7573.56,1339.71)
OUTB3/1: D36.1 U9.18 | length 452.2
  Top Layer w10: v2(7497,3964.99) 7489.39,3964.99 7488.84,3964.43 7488.84,3964.99 U9.18@7615.92,3964.99
  Bottom Layer w10: D36.1@7493.56,3708.21 7423.56,3778.21 7423.56,3889.71 7497,3963.15 v2(7497,3964.99)
OUTB3/2: D60.1 U10.18 | length 588.2
  Top Layer w10: v2(3973.56,3959.71) 3988.84,3974.99 U10.18@4245.92,3974.99
  Bottom Layer w10: v2(3973.56,3959.71) 3973.56,3848.21 D60.1@4113.56,3708.21
OUTB3/3: D84.1 U11.18 | length 361.7
  Top Layer w10: v2(4173.56,1309.71) 4198.84,1334.99 U11.18@4255.92,1334.99
  Bottom Layer w10: D84.1@4113.56,1088.22 4152.07,1088.22 4173.56,1109.71 v2(4173.56,1309.71)
OUTB3/4: D104.1 U12.18 | length 442.4
  Top Layer w10: v2(1265.75,3940.94) 1289.79,3964.99 U12.18@1425.92,3964.99
  Bottom Layer w10: v2(1265.75,3940.94) 1248.03,3923.23 1248.03,3748.03 1287.85,3708.21 D104.1@1303.56,3708.21
OUTB3/5: D120.1 U13.18 | length 363.6
  Top Layer w10: v2@1351.38,1340.55 v2(1351.38,1337.6) 1358.77,1344.99 U13.18@1435.92,1344.99
  Bottom Layer w10: D120.1@1303.56,1088.21 1303.56,1092.74 1345.56,1134.74 1347.44,1319.88 1350.84,1337.7 1351.38,1340.55 v2(1351.38,1337.6)
OUTB3/7: D136.1 U14.18 | length 496.5
  Top Layer w10: v2(9677.68,2638.33) 9695.95,2656.6 U14.18@9896.04,2656.6
  Bottom Layer w10: v2(9677.68,2638.33) 9677.68,2473.83 D136.1@9752.68,2398.83
OUTB4: D15.1 U8.21 | length 357.6
  Top Layer w10: U8.21@7931.2,1344.99 7998.28,1344.99 v2(8003.56,1339.71)
  Bottom Layer w10: v2(8003.56,1339.71) 8013.13,1330.14 8013.13,1133.94 8013.56,1133.51 8013.56,1109.71 8032.06,1109.71 D15.1@8053.56,1088.21
OUTB4/1: D39.1 U9.21 | length 387.1
  Top Layer w10: U9.21@7911.2,3964.99 7994.66,3964.99 v2(8002.95,3956.69)
  Bottom Layer w10: v2(8002.95,3956.69) 8002.95,3720.47 8010.83,3712.6 8049.18,3712.6 D39.1@8053.56,3708.21
OUTB4/2: D63.1 U10.21 | length 366.9
  Top Layer w10: U10.21@4541.2,3974.99 4618.52,3974.99 v2(4623.03,3970.47)
  Bottom Layer w10: v2(4623.03,3970.47) 4623.03,3758.74 D63.1@4673.56,3708.21
OUTB4/3: D87.1 U11.21 | length 324.9
  Top Layer w10: U11.21@4551.2,1334.99 4598.09,1334.99 v2@4605.31,1327.76
  Bottom Layer w10: v2@4605.31,1327.76 4605.31,1156.46 D87.1@4673.56,1088.21
  other v2: 4605.31,1328.44
OUTB4/4: D106.1 U12.21 | length 461.5
  Top Layer w10: U12.21@1721.2,3964.99 1898.2,3964.99 v2(1914.37,3948.82)
  Bottom Layer w10: D106.1@1863.56,3708.21 1914.37,3759.02 v2(1914.37,3948.82)
OUTB4/5: D122.1 U13.21 | length 1011.7
  Top Layer w10: U13.21@1731.2,1344.99 1799.7,1344.99 v2(1800.2,1344.49)
  Bottom Layer w10: v2(1800.2,1344.49) 1800.2,491.58 D122.1@1863.56,428.22
OUTB4/7: D138.1 U14.21 | length 428.2
  Top Layer w10: U14.21@10191.32,2656.6 10279.42,2656.6 v2(10284.45,2651.57)
  Bottom Layer w10: v2(10284.45,2651.57) 10324.43,2651.57 10373.68,2602.33 10373.68,2439.83 D138.1@10330.68,2396.83
OUTB5: D18.1 U8.24 | length 1720.4
  Top Layer w10: U8.24@7931.2,1421.76 8114.54,1421.76 8114.54,1420.33 v2(8111.69,1417.47)
  Bottom Layer w10: v2(8111.69,1417.47) 8118.82,1417.47 8833.56,702.74 8833.56,589.71 8983.56,439.71 9172.06,439.71
OUTB5/1: D42.1 U9.24 | length 2087.4
  Top Layer w10: U9.24@7911.2,4041.76 8119.84,4040.67 8125.87,4034.65 v2(8126.38,4034.65)
  Bottom Layer w10: v2(8126.38,4034.65) 8218.25,4034.65 8273.56,3979.33 8273.56,3459.71 8383.56,3349.71 8823.56,3349.71 8873.56,3299.71 8873.56,3129.71 8955.06,3048.21 D42.1@9183.56,3048.21
OUTB5/2: D66.1 U10.24 | length 1839.5
  Top Layer w10: U10.24@4541.2,4051.76 4721.86,4051.76 v2(4726.38,4047.24)
  Bottom Layer w10: v2(4726.38,4047.24) 5113.19,3660.43 5113.19,3384.84 5444.88,3053.15 5798.62,3053.15 D66.1@5803.56,3048.21
OUTB5/3: D90.1 U11.24 | length 1659.8
  Top Layer w10: U11.24@4551.2,1411.76 4681.51,1411.76 v2(4703.56,1389.71)
  Bottom Layer w10: v2(4703.56,1389.71) 5665.06,428.21 D90.1@5803.56,428.21
OUTB5/4: D108.1 U12.24 | length 1482.9
  Top Layer w10: U12.24@1721.2,4041.76 1991.51,4041.76 1993.56,4039.71 v2(1993.56,4029.71)
  Bottom Layer w10: v2(1993.56,4029.71) 2303.56,3719.71 2303.56,3099.71 2355.06,3048.21 D108.1@2423.56,3048.21
OUTB5/5: D124.1 U13.24 | length 1487.5
  Top Layer w10: U13.24@1731.2,1421.76 v2(1967.52,1421.76)
  Bottom Layer w10: v2(1967.52,1421.76) 1996.37,1421.76 2203.56,1214.57 2203.56,559.71 2335.06,428.21 D124.1@2423.56,428.21
OUTB5/7: D140.1 U14.24 | length 1920.1
  Top Layer w10: U14.24@10191.32,2733.37 10372.92,2733.37 v2(10395.67,2710.63)
  Bottom Layer w10: D140.1@10335.68,1087.83 10354.17,1106.33 10390.68,1106.33 10440.68,1156.33 10440.68,2665.62 v2(10395.67,2710.63)
OUTB6: D21.1 U8.27 | length 1421.1
  Top Layer w10: U8.27@7931.2,1498.53 v2(8212.38,1498.53)
  Bottom Layer w10: v2(8212.38,1498.53) 9062.38,1498.53 9183.56,1619.71 D21.1@9183.56,1738.21
OUTB6/1: D45.1 U9.27 | length 1429.3
  Top Layer w10: U9.27@7911.2,4118.53 7913.93,4121.26 v2(8202.17,4121.26)
  Bottom Layer w10: v2(8202.17,4121.26) 8205.11,4121.26 8283.56,4199.71 9123.56,4199.71 9183.56,4259.71 D45.1@9183.56,4358.21
OUTB6/2: D69.1 U10.27 | length 1403.5
  Top Layer w10: U10.27@4541.2,4128.53 4812.58,4128.53 v2(4837.6,4153.54)
  Bottom Layer w10: v2(4837.6,4153.54) 5677.39,4153.54 5803.56,4279.71 D69.1@5803.56,4358.22
OUTB6/3: D93.1 U11.27 | length 1420.2
  Top Layer w10: U11.27@4551.2,1488.53 4822.38,1488.53 v2(4853.56,1519.71)
  Bottom Layer w10: v2(4853.56,1519.71) 4853.56,1629.71 4883.56,1659.71 5663.56,1659.71 5742.06,1738.21 D93.1@5803.56,1738.21
OUTB6/4: D110.1 U12.27 | length 801.6
  Top Layer w10: U12.27@1721.2,4118.53 1892.38,4118.53 v2(1913.39,4139.53)
  Bottom Layer w10: v2(1913.39,4139.53) 2033.56,4259.71 2325.06,4259.71 D110.1@2423.56,4358.21
OUTB6/5: D126.1 U13.27 | length 864.1
  Top Layer w10: U13.27@1731.2,1498.53 v2(1982.38,1498.53)
  Bottom Layer w10: v2(1982.38,1498.53) 2292.38,1498.53 2429.93,1636.08 D126.1@2429.93,1744.51
OUTB6/7: D142.1 U14.27 | length 2521.1
  Top Layer w10: U14.27@10191.32,2810.15 10354.5,2810.15 v2(10400.59,2854.33)
  Bottom Layer w10: D142.1@10323.68,5017.83 10323.68,4902.33 10519.68,4706.32 10519.68,2973.43 v2(10400.59,2854.33)
OUTB7: D24.1 U8.30 | length 1397.3
  Top Layer w10: U8.30@7931.2,1575.3 8079.15,1575.3 v2(8103.56,1599.71)
  Bottom Layer w10: v2(8103.56,1599.71) 8227.84,1723.99 8227.84,2263.99 8233.56,2269.71 8583.56,2269.71 8613.56,2299.71 D24.1@8613.56,2398.21
OUTB7/1: D48.1 U9.30 | length 1365.4
  Top Layer w10: U9.30@7911.2,4195.3 8099.15,4195.3 v2(8133.56,4229.71)
  Bottom Layer w10: v2(8133.56,4229.71) 8177.17,4273.31 8177.17,4823.31 8372.07,5018.22 D48.1@8613.56,5018.22
OUTB7/2: D72.1 U10.30 | length 1373
  Top Layer w10: U10.30@4541.2,4205.3 4729.15,4205.3 v2(4793.56,4269.71)
  Bottom Layer w10: v2(4793.56,4269.71) 4793.56,4839.71 4972.07,5018.22 D72.1@5243.56,5018.22
OUTB7/3: D96.1 U11.30 | length 1388
  Top Layer w10: U11.30@4551.2,1565.3 v2(4665.35,1565.3)
  Bottom Layer w10: v2(4665.35,1565.3) 4699.15,1565.3 4743.56,1609.71 4743.56,2099.71 4863.56,2219.71 5173.56,2219.71 5243.56,2289.71 D96.1@5243.56,2398.22
OUTB7/4: D112.1 U12.30 | length 1079.3
  Top Layer w10: U12.30@1721.2,4195.3 v2@1859.15,4195.3 ; v2(1849.78,4195.11) v2@1858.96,4195.11
  Bottom Layer w10: v2(1849.78,4195.11) 1858.39,4195.11 1982.28,4319.01 1982.28,4782.48 1982.28,4800.99 1863.56,4919.71 D112.1@1863.56,5018.21
OUTB7/5: D128.1 U13.30 | length 985.3
  Top Layer w10: U13.30@1731.2,1575.3 v2(1849.15,1575.3)
  Bottom Layer w10: v2(1849.15,1575.3) 1909.45,1635.6 1909.45,2357.41 D128.1@1866.84,2400.02
OUTB7/7: D144.1 U14.30 | length 1064.8
  Top Layer w10: U14.30@10191.32,2886.92 10320.27,2886.92 v2(10329.72,2896.37)
  Bottom Layer w10: D144.1@10325.68,3716.83 10325.68,3614.33 10450.79,3489.22 10450.79,3017.44 v2(10329.72,2896.37)
OUTG0: D1.1 U8.7 | length 274.9
  Top Layer w10: v2(7493.56,1649.71) 7516.79,1626.48 U8.7@7635.92,1626.48
  Bottom Layer w10: v2(7493.56,1649.71) D1.1@7493.56,1738.21 7495.08,1739.73 7495.08,1772.02
OUTG0/1: D25.1 U9.7 | length 218.7
  Top Layer w10: v2(7493.56,4279.71) 7523.56,4249.71 7612.69,4249.71 U9.7@7615.92,4246.48
  Bottom Layer w10: v2(7493.56,4279.71) D25.1@7493.56,4358.21 D25.1@7497.66,4358.21
OUTG0/2: D49.1 U10.7 | length 220.5
  Top Layer w10: v2(4113.56,4279.71) 4136.79,4256.48 U10.7@4245.92,4256.48
  Bottom Layer w10: v2(4113.56,4279.71) D49.1@4113.56,4358.21
OUTG0/3: D73.1 U11.7 | length 244.6
  Top Layer w10: v2(4113.56,1649.71) 4146.79,1616.48 U11.7@4255.92,1616.48
  Bottom Layer w10: v2(4113.56,1649.71) D73.1@4113.56,1738.21
OUTG1: D4.1 U8.10 | length 1855.7
  Top Layer w10: v2(7253.56,1649.71) 7353.56,1549.71 U8.10@7635.92,1549.71
  Bottom Layer w10: D4.1@6363.56,2398.21 6363.56,2302.44 6396.29,2269.71 6933.56,2269.71 7223.56,1979.71 7223.56,1679.71 v2(7253.56,1649.71)
OUTG1/1: D28.1 U9.10 | length 1913.4
  Top Layer w10: v2(7303.56,4279.71) 7413.56,4169.71 U9.10@7615.92,4169.71
  Bottom Layer w10: D28.1@6363.56,5018.21 6363.56,4949.71 6403.56,4909.71 7133.56,4909.71 7303.56,4739.71 v2(7303.56,4279.71)
OUTG1/2: D52.1 U10.10 | length 1966.1
  Top Layer w10: v2(3913.56,4279.71) 4013.56,4179.71 U10.10@4245.92,4179.71
  Bottom Layer w10: D52.1@2983.56,5018.22 2983.56,4949.71 3013.56,4919.71 3813.56,4919.71 3913.56,4819.71 v2(3913.56,4279.71)
OUTG1/3: D76.1 U11.10 | length 1955.3
  Top Layer w10: v2(3893.56,1629.71) 3983.56,1539.71 U11.10@4255.92,1539.71
  Bottom Layer w10: D76.1@2983.56,2398.21 2983.56,2265.88 3079.43,2170.01 3779.8,2170.01 3893.56,2056.24 v2(3893.56,1629.71)
OUTG2: D7.1 U8.13 | length 1431.7
  Top Layer w10: v2(7216.79,1472.94) U8.13@7635.92,1472.94
  Bottom Layer w10: D7.1@6363.56,1088.21 6502.06,1088.21 6886.79,1472.94 v2(7216.79,1472.94)
OUTG2/1: D31.1 U9.13 | length 1442.2
  Top Layer w10: v2(7263.56,4129.71) 7300.33,4092.94 U9.13@7615.92,4092.94
  Bottom Layer w10: D31.1@6363.56,3708.21 6432.06,3708.21 6853.56,4129.71 v2(7263.56,4129.71)
OUTG2/2: D55.1 U10.13 | length 1425.9
  Top Layer w10: v2(3800.33,4102.94) U10.13@4245.92,4102.94
  Bottom Layer w10: D55.1@2983.56,3708.22 3082.07,3708.22 3476.79,4102.94 v2(3800.33,4102.94)
OUTG2/3: D79.1 U11.13 | length 1427.6
  Top Layer w10: v2(3780.33,1462.94) U11.13@4255.92,1462.94
  Bottom Layer w10: D79.1@2983.56,1088.21 3102.06,1088.21 3476.79,1462.94 v2(3780.33,1462.94)
OUTG3: D10.1 U8.16 | length 1413.8
  Top Layer w10: v2(7393.56,1329.71) 7460.02,1396.17 U8.16@7635.92,1396.17
  Bottom Layer w10: D10.1@6933.56,428.21 7022.06,428.21 7143.56,549.71 7143.56,1079.71 v2(7393.56,1329.71)
OUTG3/1: D34.1 U9.16 | length 1468.1
  Top Layer w10: v2(7273.56,3999.71) 7289.37,4015.75 U9.16@7615.92,4016.17
  Bottom Layer w10: D34.1@6933.56,3048.22 6979.22,3048.22 7023.56,3092.56 7023.56,3747.66 7273.56,3997.66 v2(7273.56,3999.71)
OUTG3/2: D58.1 U10.16 | length 1481.3
  Top Layer w10: v2@3885.08,4012.05 3898.62,4025.59 U10.16@4245.92,4026.17
  Bottom Layer w10: D58.1@3553.56,3048.22 3582.07,3048.22 3663.56,3129.71 3663.56,3789.71 v2(3883.56,4009.71)
OUTG3/3: D82.1 U11.16 | length 1401.1
  Top Layer w10: v2(4003.56,1309.71) 4090.02,1386.17 U11.16@4255.92,1386.17
  Bottom Layer w10: D82.1@3553.56,428.21 3642.06,428.21 3813.56,599.71 3813.56,689.71 4003.56,879.71 v2(4003.56,1309.71)
OUTG4: D13.1 U8.23 | length 1393.8
  Top Layer w10: U8.23@7931.2,1396.17 8067.1,1396.17 v2(8093.56,1369.71)
  Bottom Layer w10: v2(8093.56,1369.71) 8403.56,1059.71 8403.56,529.71 8505.06,428.21 D13.1@8613.56,428.21
OUTG4/1: D37.1 U9.23 | length 1576.6
  Top Layer w10: U9.23@7911.2,4016.17 8083.24,4016.17 v2(8097.44,4004.92)
  Bottom Layer w10: v2(8097.44,4004.92) 8209.33,4003.94 8223.56,3989.71 8223.56,3179.71 8293.56,3109.71 8453.56,3109.71 8515.06,3048.21 D37.1@8613.56,3048.21
OUTG4/2: D61.1 U10.23 | length 1354.6
  Top Layer w10: U10.23@4541.2,4026.17 4686.43,4026.17 v2(4704.72,4007.87)
  Bottom Layer w10: v2(4704.72,4007.87) 5093.56,3621.06 5093.56,3198.21 D61.1@5243.56,3048.21 ; v2@4711.61,4002.95 v2@4711.67,4002.95
OUTG4/3: D85.1 U11.23 | length 1353.6
  Top Layer w10: U11.23@4551.2,1386.17 4595.15,1386.17 4595.27,1386.28 4619.3,1386.28 4619.41,1386.17 4657.1,1386.17 4657.1,1383.25 4661.35,1379 v2(4661.64,1379)
  Bottom Layer w10: v2(4661.64,1379) 4661.64,1371.63 4799.55,1233.72 4800.56,1233.72 4817.55,1216.74 4817.55,1215.72 5053.56,979.71 5053.56,539.71 5165.06,428.22 D85.1@5243.56,428.22
OUTG5: D16.1 U8.26 | length 1411.7
  Top Layer w10: U8.26@7931.2,1472.94 8166.79,1472.94 v2(8190.02,1449.71)
  Bottom Layer w10: v2(8190.02,1449.71) 8713.56,1449.71 9075.06,1088.21 D16.1@9183.56,1088.21
OUTG5/1: D40.1 U9.26 | length 1491.4
  Top Layer w10: U9.26@7911.2,4092.94 7913.93,4095.67 v2(8232.28,4095.67)
  Bottom Layer w10: v2(8232.28,4095.67) 8282.65,4095.67 8363.56,4014.76 8363.56,3909.71 8992.07,3909.71 D40.1@9183.56,3718.21
OUTG5/2: D64.1 U10.26 | length 1428.3
  Top Layer w10: U10.26@4541.2,4102.94 4542.59,4104.33 v2(4835.63,4104.33)
  Bottom Layer w10: v2(4835.63,4104.33) 5068.9,4104.33 5466.54,3706.69 5802.04,3706.69 D64.1@5803.56,3708.21
OUTG5/3: D88.1 U11.26 | length 1407.6
  Top Layer w10: U11.26@4551.2,1462.94 4551.47,1462.67 v2(4827.99,1462.67)
  Bottom Layer w10: v2(4827.99,1462.67) 5280.6,1462.67 5655.06,1088.21 D88.1@5803.56,1088.21
OUTG6: D19.1 U8.29 | length 1943.4
  Top Layer w10: U8.29@7931.2,1549.71 8113.56,1549.71 v2(8133.56,1569.71)
  Bottom Layer w10: v2(8133.56,1569.71) 8252.56,1688.71 8252.56,2235.99 8244.84,2243.7 8244.84,2249.71 9035.06,2249.71 D19.1@9183.56,2398.21
OUTG6/1: D43.1 U9.29 | length 2003.7
  Top Layer w10: U9.29@7911.2,4169.71 8133.56,4169.71 v2(8173.56,4209.71)
  Bottom Layer w10: v2(8173.56,4209.71) 8208.66,4244.81 8208.66,4794.81 8313.56,4899.71 9163.56,4899.71 9183.56,4919.71 D43.1@9183.56,5018.22
OUTG6/2: D67.1 U10.29 | length 1972
  Top Layer w10: U10.29@4541.2,4179.71 4763.56,4179.71 v2(4823.82,4239.97)
  Bottom Layer w10: v2(4823.82,4239.97) 4823.82,4799.97 4853.56,4829.71 4953.56,4929.71 5773.56,4929.71 5803.56,4959.71 D67.1@5803.56,5018.22
OUTG6/3: D91.1 U11.29 | length 1990.6
  Top Layer w10: U11.29@4551.2,1539.71 4753.56,1539.71 v2(4773.56,1559.71)
  Bottom Layer w10: v2(4773.56,1559.71) 4773.56,2104.43 4868.84,2199.71 5713.56,2199.71 5803.56,2289.71 D91.1@5803.56,2398.21
OUTG7: D22.1 U8.32 | length 208.8
  Top Layer w10: U8.32@7931.2,1626.48 v2(8010.33,1626.48)
  Bottom Layer w10: v2(8010.33,1626.48) 8053.56,1669.71 D22.1@8053.56,1738.21
OUTG7/1: D46.1 U9.32 | length 235.6
  Top Layer w10: U9.32@7911.2,4246.48 7914.43,4249.71 v2(7998.03,4249.71)
  Bottom Layer w10: v2(7998.03,4249.71) 8025.3,4249.71 8053.56,4277.97 D46.1@8053.56,4358.22
OUTG7/2: D70.1 U10.32 | length 226.3
  Top Layer w10: U10.32@4541.2,4256.48 4541.61,4256.89 v2(4620.08,4256.89)
  Bottom Layer w10: v2(4620.08,4256.89) 4660.74,4256.89 4673.56,4269.71 D70.1@4673.56,4358.22
OUTG7/3: D94.1 U11.32 | length 205.5
  Top Layer w10: U11.32@4551.2,1616.48 4606.64,1616.48 v2(4615.16,1625)
  Bottom Layer w10: v2(4615.16,1625) 4673.56,1683.4 D94.1@4673.56,1738.21 D94.1@4674,1737.77
OUTR0: D2.1 U8.8 | length 1024.2
  Top Layer w10: v2(7413.56,1649.71) 7462.38,1600.89 U8.8@7635.92,1600.89
  Bottom Layer w10: v2(7413.56,1649.71) 7413.56,2209.71 7493.56,2289.71 D2.1@7493.56,2398.21
OUTR0/1: D26.1 U9.8 | length 980.9
  Top Layer w10: v2(7425.92,4279.71) 7484.74,4220.89 U9.8@7615.92,4220.89
  Bottom Layer w10: v2(7425.92,4279.71) 7425.92,4867.35 7493.56,4934.98 D26.1@7493.56,5018.21
OUTR0/2: D50.1 U10.8 | length 984.2
  Top Layer w10: v2(4043.56,4279.71) 4092.38,4230.89 U10.8@4245.92,4230.89
  Bottom Layer w10: 4033.56,4289.71 4033.56,4829.71 4113.56,4909.71 D50.1@4113.56,5018.22
OUTR0/3: D74.1 U11.8 | length 1048.4
  Top Layer w10: v2(4023.56,1639.71) 4072.38,1590.89 U11.8@4255.92,1590.89
  Bottom Layer w10: v2(4023.56,1639.71) 4023.56,2229.71 4113.56,2319.71 D74.1@4113.56,2398.21
OUTR1: D5.1 U8.11 | length 831.2
  Top Layer w10: v2(7163.56,1649.71) 7289.15,1524.12 U8.11@7635.92,1524.12
  Bottom Layer w10: D5.1@6933.56,1738.21 6933.56,1669.71 6953.56,1649.71 v2(7163.56,1649.71)
OUTR1/1: D29.1 U9.11 | length 802.4
  Top Layer w10: v2(7243.56,4279.71) 7379.15,4144.12 U9.11@7615.92,4144.12
  Bottom Layer w10: D29.1@6931,4358.21 D29.1@6933.56,4358.21 6933.56,4309 6962.85,4279.71 v2(7243.56,4279.71)
OUTR1/2: D53.1 U10.11 | length 811.2
  Top Layer w10: v2(3853.56,4279.71) 3979.15,4154.12 U10.11@4245.92,4154.12
  Bottom Layer w10: D53.1@3553.56,4358.22 3553.56,4299.71 3573.56,4279.71 v2(3853.56,4279.71)
OUTR1/3: D77.1 U11.11 | length 832.7
  Top Layer w10: v2(3823.56,1629.71) 3939.15,1514.12 U11.11@4255.92,1514.12
  Bottom Layer w10: D77.1@3556.8,1738.21 D77.1@3553.56,1738.21 3553.56,1679.71 3593.56,1639.71 3813.56,1639.71 v2(3823.56,1629.71)
OUTR2: D8.1 U8.14 | length 851.1
  Top Layer w10: v2(7308.28,1389.71) 7365.92,1447.35 U8.14@7635.92,1447.35
  Bottom Layer w10: D8.1@6933.56,1088.21 7006.79,1088.21 v2(7308.28,1389.71)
